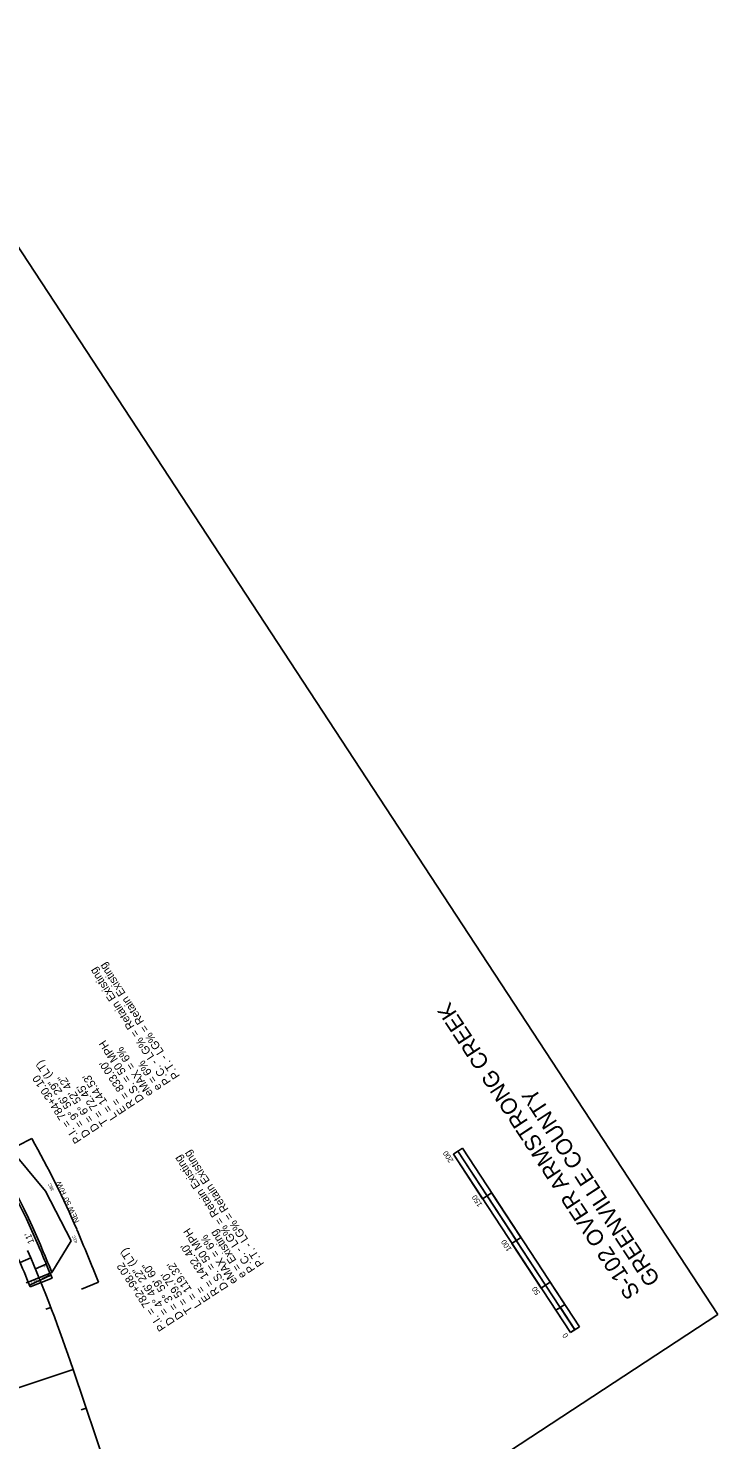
# Model space of a CAD drawing. Extents: x 1551641 to 1624343, y 1119533 to 1136600.
# Drawn here: x 1552901 to 1553547, y 1133695 to 1135018 of the extents above; entities that cross this region are included whole.
import ezdxf

# ---------------------------------------------------------------- set-up
doc = ezdxf.new("R2010")
doc.units = 0
for name, color, linetype in [('RD_HC_Cl', 7, 'Continuous'), ('RD_HC_Data', 7, 'Continuous'), ('RD_HC_Data_Tic', 7, 'Continuous'), ('RD_PD_ALT1_TX', 7, 'Continuous'), ('RD_PD_CstnLmt', 7, 'Continuous'), ('RD_PD_CstnLmt_TX', 7, 'Continuous'), ('RD_PD_Final_TrvlWay', 7, 'Continuous'), ('RD_PD_Final_TX', 7, 'Continuous'), ('RD_PD_PaveShd', 7, 'Continuous'), ('RD_PD_RW', 7, 'Continuous'), ('RD_SHT_ShtClip', 7, 'Continuous'), ('RD_SHT_TX', 7, 'Continuous'), ('RD_TX_Pipe_ElevEX', 7, 'Continuous')]:
    doc.layers.add(name, color=color, linetype=linetype)

msp = doc.modelspace()

# ---------------------------------------------------------------- linework, layer by layer
at = {"layer": 'RD_HC_Cl'}
msp.add_line((1553070, 1133383.1), (1552943.4, 1133761.1), dxfattribs=at)
msp.add_arc((1551585.1, 1133306.1), 1432.4, 18.5195, 23.2924, dxfattribs=at)
at = {"layer": 'RD_HC_Data'}
msp.add_line((1552943.4, 1133761.1), (1552844.2, 1133727.9), dxfattribs=at)
at = {"layer": 'RD_HC_Data_Tic'}
for p, q in [((1552922.5, 1133819.1), (1552917.9, 1133817.4)), ((1552955.5, 1133724.8), (1552950.8, 1133723.2))]:
    msp.add_line(p, q, dxfattribs=at)
at = {"layer": 'RD_PD_ALT1_TX'}
for p, q in [((1552893.7, 1133861.2), (1552903.8, 1133865.5)), ((1552908.1, 1133855.4), (1552918.2, 1133859.6))]:
    msp.add_line(p, q, dxfattribs=at)
at = {"layer": 'RD_PD_CstnLmt'}
for p, q in [((1552917.6, 1133928), (1552883.6, 1133968.8)), ((1552941.6, 1133881.6), (1552917.6, 1133928)), ((1552941.6, 1133881.6), (1552923.5, 1133851.9))]:
    msp.add_line(p, q, dxfattribs=at)
at = {"layer": 'RD_PD_Final_TrvlWay'}
msp.add_line((1552901.3, 1133842.9), (1552921.7, 1133851.2), dxfattribs=at)
for centre, radius, start, end in [((1552135.7, 1133543.2), 844, 23.2924, 33.2337), ((1551585.1, 1133306.1), 1443.4, 22.1864, 23.2924), ((1551585.1, 1133306.1), 1421.4, 22.1864, 23.2924)]:
    msp.add_arc(centre, radius, start, end, dxfattribs=at)
at = {"layer": 'RD_PD_PaveShd'}
for p, q in [((1552921.7, 1133851.2), (1552923.5, 1133851.9)), ((1552899.4, 1133842.1), (1552901.3, 1133842.9))]:
    msp.add_line(p, q, dxfattribs=at)
for centre, radius, start, end in [((1552135.7, 1133543.2), 846, 23.2924, 33.2337), ((1551585.1, 1133306.1), 1445.4, 22.1864, 23.2924)]:
    msp.add_arc(centre, radius, start, end, dxfattribs=at)
at = {"layer": 'RD_PD_RW'}
for p, q in [((1552891.3, 1133970.5), (1552904.6, 1133977.3)), ((1552951.3, 1133836.3), (1552967, 1133842.7))]:
    msp.add_line(p, q, dxfattribs=at)
for centre, radius, start, end in [((1552135.7, 1133543.2), 883, 23.2924, 29.4522), ((1551585.1, 1133306.1), 1482.4, 21.2201, 23.2924)]:
    msp.add_arc(centre, radius, start, end, dxfattribs=at)
at = {"layer": 'RD_SHT_ShtClip'}
for p, q in [((1552560.8, 1135318), (1553547.3, 1133812.4)), ((1553547.3, 1133812.4), (1552627.2, 1133209.5))]:
    msp.add_line(p, q, dxfattribs=at)
at = {"layer": 'RD_SHT_TX'}
for p, q in [((1553299.6, 1133962.7), (1553308, 1133968.2)), ((1553307.1, 1133967.6), (1553307.1, 1133967.6)), ((1553417.6, 1133801), (1553308, 1133968.2)), ((1553409.2, 1133795.5), (1553299.6, 1133962.7)), ((1553386, 1133840), (1553303.8, 1133965.4)), ((1553304.6, 1133966), (1553304.6, 1133966)), ((1553305.5, 1133966.5), (1553305.5, 1133966.5)), ((1553306.3, 1133967.1), (1553306.3, 1133967.1)), ((1553327, 1133920.9), (1553335.4, 1133926.4)), ((1553335.4, 1133926.4), (1553335.4, 1133926.4)), ((1553354.4, 1133879.1), (1553362.8, 1133884.6)), ((1553381.8, 1133837.3), (1553390.2, 1133842.8)), ((1553413.4, 1133798.2), (1553386, 1133840)), ((1553390.2, 1133842.8), (1553390.2, 1133842.8)), ((1553395.5, 1133816.4), (1553403.9, 1133821.9)), ((1553409.2, 1133795.5), (1553417.6, 1133801))]:
    msp.add_line(p, q, dxfattribs=at)
for points in [[(1553327, 1133920.9), (1553299.6, 1133962.7), (1553303.8, 1133965.4), (1553331.2, 1133923.6)], [(1553358.6, 1133881.8), (1553331.2, 1133923.6), (1553335.4, 1133926.4), (1553362.8, 1133884.6)], [(1553381.8, 1133837.3), (1553354.4, 1133879.1), (1553358.5, 1133881.9), (1553386, 1133840)], [(1553399.7, 1133819.1), (1553386, 1133840), (1553390.2, 1133842.8), (1553403.9, 1133821.9)], [(1553409.2, 1133795.5), (1553395.5, 1133816.4), (1553399.8, 1133819.2), (1553413.5, 1133798.3)]]:
    msp.add_lwpolyline(points, close=True, dxfattribs=at)
at = {"layer": 'RD_TX_Pipe_ElevEX'}
for q in [(1552922.4, 1133849.5), (1552902.5, 1133839.9)]:
    msp.add_line((1552912.4, 1133844.8), q, dxfattribs=at)
msp.add_lwpolyline([(1552903.2, 1133838.3), (1552901.3, 1133842.9), (1552921.7, 1133851.2), (1552923.6, 1133846.6)], close=True, dxfattribs=at)
msp.add_lwpolyline([(1552902.5, 1133839.9), (1552908.9, 1133843.1), (1552911.7, 1133844.4), (1552918.4, 1133847.7), (1552921, 1133848.9), (1552921.4, 1133849.1), (1552922.4, 1133849.5)], dxfattribs=at)

# ---------------------------------------------------------------- texts
at = {"layer": 'RD_HC_Data'}
for s, p in [('P.T. - LG% = Retain Existing', (1553043.6, 1134036)), ('P.C. - LG% = Retain Existing', (1553035.2, 1134030.5)), ('D.S. = 50 MPH', (1553010.1, 1134014.1)), ('eMAX = 6%', (1553018.5, 1134019.6)), ('    = 9%%d 56\' 29" (LT)', (1552959.9, 1133981.2)), ("R = 833.00'", (1553001.7, 1134008.6)), ('e = 6%', (1553026.8, 1134025)), ('P.I. = 784+30.10', (1552951.6, 1133975.7)), ('D = 6%%d 52\' 42"', (1552968.3, 1133986.7)), ("L = 144.53'", (1552985, 1133997.6)), ("T = 72.45'", (1552976.6, 1133992.2)), ('E = ', (1552993.4, 1134003.1)), ('D', (1552959.9, 1133981.2)), ('P.T. - LG% = Retain Existing', (1553122.6, 1133860.1)), ('P.C. - LG% = Retain Existing', (1553114.3, 1133854.6)), ('D.S. = 50 MPH', (1553089.2, 1133838.1)), ('e = Existing', (1553105.9, 1133849.1)), ("R = 1432.40'", (1553080.8, 1133832.7)), ('eMAX = 6%', (1553097.6, 1133843.6)), ('    = 4%%d 46\' 22" (LT)', (1553039, 1133805.3)), ('P.I. = 782+98.02', (1553030.6, 1133799.8)), ('D = 3%%d 59\' 60"', (1553047.4, 1133810.7)), ("T = 59.70'", (1553055.7, 1133816.2)), ("L = 119.32'", (1553064.1, 1133821.7)), ('E = ', (1553072.5, 1133827.2)), ('D', (1553039, 1133805.3))]:
    msp.add_text(s, height=7.5, rotation=123.2337, dxfattribs=at).set_placement(p)
at = {"layer": 'RD_PD_ALT1_TX'}
msp.add_text('+06', height=1.5, rotation=202.9864, dxfattribs=at).set_placement((1552918.5, 1133859.4))
at = {"layer": 'RD_PD_CstnLmt_TX'}
for s, rotation, p in [('38C', 116.2053, (1552925.8, 1133929)), ('41C', 112.9864, (1552947.7, 1133880.2))]:
    msp.add_text(s, height=3, rotation=rotation, dxfattribs=at).set_placement(p)
at = {"layer": 'RD_PD_Final_TX'}
msp.add_text("11'", height=6, rotation=113.1378, dxfattribs=at).set_placement((1552907.1, 1133880.2))
at = {"layer": 'RD_PD_RW'}
msp.add_text("NEW 50' R/W", height=5, rotation=114.983, dxfattribs=at).set_placement((1552949.4, 1133899.7))
at = {"layer": 'RD_SHT_TX'}
for s, height, rotation, p in [('S-102 OVER ARMSTRONG CREEK', 15, 123.2337, (1553475.1, 1133832.9)), ('GREENVILLE COUNTY', 15, 123.2337, (1553493.9, 1133845.2)), ('200', 5, 123.233, (1553299.9, 1133956.8)), ('150', 5, 123.2298, (1553327, 1133915.4)), ('100', 5, 123.2311, (1553354.4, 1133873.6)), ('50', 5, 123.2337, (1553381.1, 1133832.8)), ('0', 5, 123.2303, (1553407.6, 1133792.5))]:
    msp.add_text(s, height=height, rotation=rotation, dxfattribs=at).set_placement(p)
at = {"layer": 'RD_TX_Pipe_ElevEX'}
for s, p in [('+5.5909', (1552913.9, 1133846.1)), ('-6.8909', (1552903.7, 1133841.4))]:
    msp.add_text(s, height=1.5, rotation=22.1864, dxfattribs=at).set_placement(p)

doc.saveas('drawing.dxf')
